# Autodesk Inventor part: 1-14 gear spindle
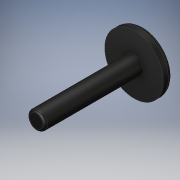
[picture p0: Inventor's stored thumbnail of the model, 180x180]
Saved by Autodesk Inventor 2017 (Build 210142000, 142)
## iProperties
Created: 2017-04
Part Number: 1-14 gear spindle
Material: Generic
Document SubType Name: Modeling
Designer: Stan
Density: 1 g/cm^3
Appearance: Glossy - Black
Author: Stan
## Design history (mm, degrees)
sketch "Sketch1"
  geometry: C1 r 9.525 at (0, 0); 1 further point
  constraints: 1 centre point, 1 coincident
  dimensions: "d0" = 19.05 diameter of C1
extrude "Extrusion1" new body sketch "Sketch1" distance "d1" = 3.175; taper "d2" = 0 deg
sketch "Sketch2"
  geometry: C1 r 2.921 at (0, 0); 1 further point
  constraints: 1 centre point, 1 coincident
  dimensions: "d3" = 5.842 diameter of C1
extrude "Extrusion2" join sketch "Sketch2" distance "d4" = 31.75; taper "d5" = 0 deg
fillet "Fillet1" dims "d6" = 1.5875
fillet "Fillet2" dims "d7" = 0.79375
body "Solid1"
